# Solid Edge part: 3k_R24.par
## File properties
Author: Türk
Template: iso part.par
Last saved by: Türk
Revision: 2
Application: Solid Edge
Accuracy: 0,990
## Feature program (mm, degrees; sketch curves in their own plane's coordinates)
pattern "PatternOccurrence_1"  XOffset = 12 deg
pattern "PatternOccurrence_2"  XCount = 30; XOffset = 12 deg
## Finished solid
Body 1: solid body, 183 faces, 542 edges, 360 vertices.
  Faces by surface: plane 122, cylinder 61
  Edges by curve: line 420, circle 122
Bounding box of the edges (mm): 56.000 x 30.000 x 55.805, from (-28, 0, -27.9026) to (28, 30, 27.9026).
Cylindrical faces by radius (mm): R14 x1, R24 x30, R28 x30
Planar faces by outward normal: +y 1, -y 1, oblique 120
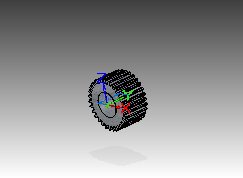
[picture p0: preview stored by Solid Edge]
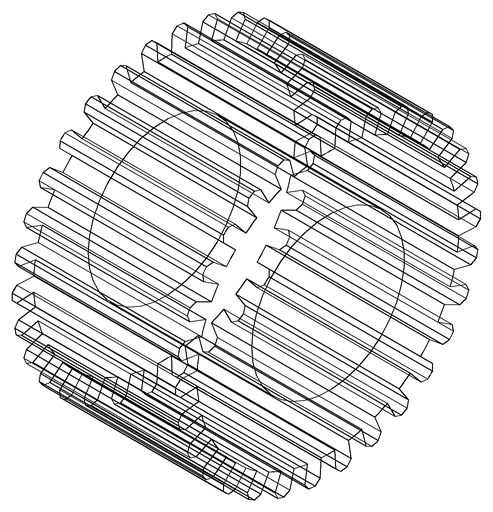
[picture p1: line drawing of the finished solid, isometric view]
